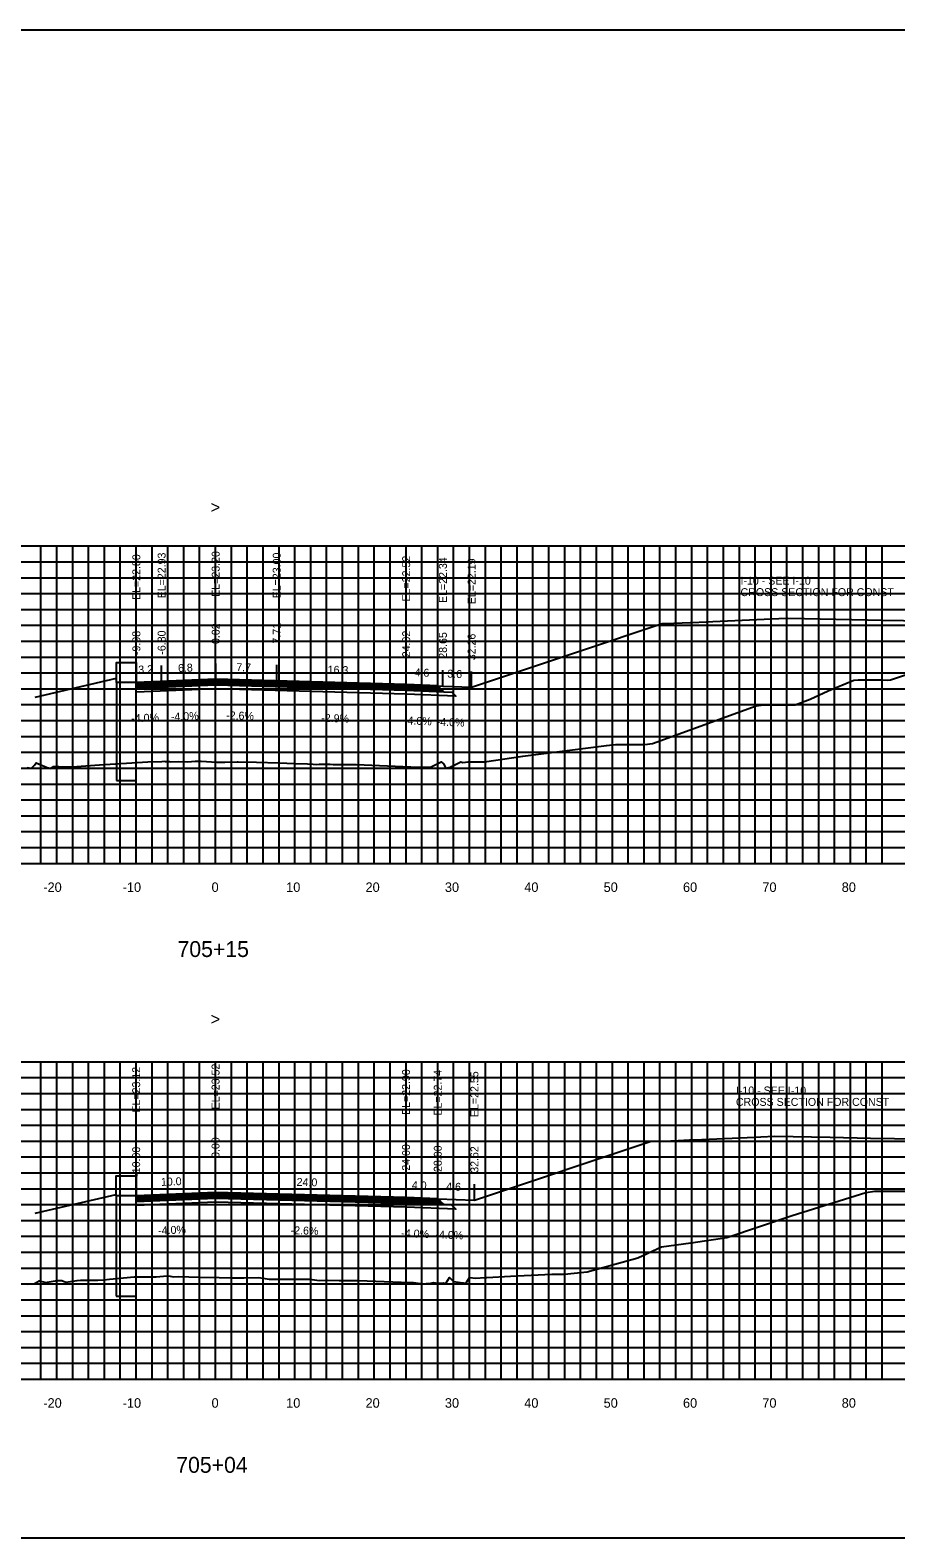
# Model space of a CAD drawing. Extents: x 1797518 to 1804843, y 248068 to 251132.
# Drawn here: x 1803627.6 to 1803736.7, y 250079.4 to 250269.4 of the extents above; entities that cross this region are included whole.
import ezdxf

# ---------------------------------------------------------------- set-up
doc = ezdxf.new("R2010")
doc.units = 0
for name, color, linetype in [('1', 7, 'Continuous'), ('10', 7, 'Continuous'), ('3', 7, 'Continuous'), ('4', 7, 'Continuous'), ('60', 7, 'Continuous'), ('BASE', 7, 'Continuous'), ('CL-CNST', 7, 'Continuous'), ('Level 62', 7, 'Continuous'), ('LOWER BINDER', 7, 'Continuous'), ('M-ROADS', 7, 'Continuous'), ('UPPER BINDER', 7, 'Continuous'), ('WEARING', 7, 'Continuous')]:
    doc.layers.add(name, color=color, linetype=linetype)

msp = doc.modelspace()

# ---------------------------------------------------------------- linework, layer by layer
for p, q in [((1803641.02, 250187.23), (1803641.02, 250189.23)), ((1803644.21, 250187.36), (1803644.21, 250189.36)), ((1803651.02, 250187.63), (1803651.02, 250189.63)), ((1803658.71, 250187.43), (1803658.71, 250189.43)), ((1803675.02, 250186.96), (1803675.02, 250188.96)), ((1803679.65, 250186.77), (1803679.65, 250188.77)), ((1803683.26, 250186.63), (1803683.26, 250188.63)), ((1803641, 250122.55), (1803641, 250124.55)), ((1803651, 250122.95), (1803651, 250124.95)), ((1803675, 250122.33), (1803675, 250124.33)), ((1803679, 250122.17), (1803679, 250124.17)), ((1803683.62, 250121.99), (1803683.62, 250123.99))]:
    msp.add_line(p, q)
msp.add_lwpolyline([(1803501, 250079.43), (1803801, 250079.43), (1803801, 250269.43), (1803501, 250269.43)], close=True)
at = {"layer": '3'}
for p, q in [((1803628.28, 250185.38), (1803638.52, 250187.78)), ((1803628.28, 250120.33), (1803638.5, 250122.72))]:
    msp.add_line(p, q, dxfattribs=at)
at = {"layer": '60'}
for p, q in [((1803501, 250164.43), (1803801, 250164.43)), ((1803631, 250164.37), (1803631, 250164.43)), ((1803641, 250164.37), (1803641, 250164.43)), ((1803651, 250164.37), (1803651, 250164.43)), ((1803661, 250164.37), (1803661, 250164.43)), ((1803671, 250164.37), (1803671, 250164.43)), ((1803681, 250164.37), (1803681, 250164.43)), ((1803691, 250164.37), (1803691, 250164.43)), ((1803701, 250164.37), (1803701, 250164.43)), ((1803711, 250164.37), (1803711, 250164.43)), ((1803721, 250164.37), (1803721, 250164.43)), ((1803731, 250164.37), (1803731, 250164.43)), ((1803501, 250099.43), (1803801, 250099.43)), ((1803631, 250099.37), (1803631, 250099.43)), ((1803641, 250099.37), (1803641, 250099.43)), ((1803651, 250099.37), (1803651, 250099.43)), ((1803661, 250099.37), (1803661, 250099.43)), ((1803671, 250099.37), (1803671, 250099.43)), ((1803681, 250099.37), (1803681, 250099.43)), ((1803691, 250099.37), (1803691, 250099.43)), ((1803701, 250099.37), (1803701, 250099.43)), ((1803711, 250099.37), (1803711, 250099.43)), ((1803721, 250099.37), (1803721, 250099.43)), ((1803731, 250099.37), (1803731, 250099.43))]:
    msp.add_line(p, q, dxfattribs=at)
at = {"layer": 'BASE'}
for points in [[(1803641.02, 250186.51), (1803651.02, 250186.91), (1803675.02, 250186.24), (1803679.77, 250186.05), (1803680.77, 250186.01), (1803681.29, 250185.48), (1803675.02, 250185.74), (1803651.02, 250186.41), (1803641.02, 250186.01)], [(1803641, 250121.83), (1803651, 250122.23), (1803675, 250121.61), (1803679.75, 250121.42), (1803680.75, 250121.38), (1803681.27, 250120.86), (1803675, 250121.11), (1803651, 250121.73), (1803641, 250121.33)]]:
    msp.add_lwpolyline(points, close=True, dxfattribs=at)
at = {"layer": 'CL-CNST'}
for points in [[(1803683.26, 250186.63), (1803696.86, 250191.16), (1803707.29, 250194.64), (1803707.73, 250194.66), (1803710.82, 250194.79), (1803711.03, 250194.8), (1803712.84, 250194.88), (1803713.67, 250194.91), (1803722.92, 250195.31), (1803723.11, 250195.31), (1803725.23, 250195.27), (1803733.17, 250195.12), (1803735.03, 250195.08), (1803742.97, 250194.94)], [(1803641.02, 250187.23), (1803644.21, 250187.36), (1803651.02, 250187.63), (1803658.71, 250187.43), (1803675.02, 250186.96), (1803679.65, 250186.77), (1803683.26, 250186.63)], [(1803683.62, 250121.99), (1803705.77, 250129.37), (1803708.35, 250129.48), (1803709.3, 250129.52), (1803710.74, 250129.59), (1803711.32, 250129.61), (1803717.97, 250129.89), (1803721.42, 250130.04), (1803728.46, 250129.91), (1803733.53, 250129.82), (1803739.57, 250129.71)], [(1803641, 250122.55), (1803651, 250122.95), (1803675, 250122.33), (1803679, 250122.17), (1803683.62, 250121.99)]]:
    msp.add_lwpolyline(points, dxfattribs=at)
for points in [[(1803641.02, 250187.23), (1803638.52, 250187.23), (1803638.52, 250189.73), (1803641.02, 250189.73)], [(1803638.52, 250174.87), (1803641.02, 250174.87), (1803641.02, 250187.23), (1803638.52, 250187.23)], [(1803641, 250122.55), (1803638.5, 250122.55), (1803638.5, 250125.05), (1803641, 250125.05)], [(1803638.5, 250109.87), (1803641, 250109.87), (1803641, 250122.55), (1803638.5, 250122.55)]]:
    msp.add_lwpolyline(points, close=True, dxfattribs=at)
at = {"layer": 'Level 62'}
for p, q in [((1803501, 250204.43), (1803801, 250204.43)), ((1803629, 250164.43), (1803629, 250204.43)), ((1803631, 250164.43), (1803631, 250204.43)), ((1803633, 250164.43), (1803633, 250204.43)), ((1803635, 250164.43), (1803635, 250204.43)), ((1803637, 250164.43), (1803637, 250204.43)), ((1803639, 250164.43), (1803639, 250204.43)), ((1803641, 250164.43), (1803641, 250204.43)), ((1803643, 250164.43), (1803643, 250204.43)), ((1803645, 250164.43), (1803645, 250204.43)), ((1803647, 250164.43), (1803647, 250204.43)), ((1803649, 250164.43), (1803649, 250204.43)), ((1803651, 250164.43), (1803651, 250204.43)), ((1803653, 250164.43), (1803653, 250204.43)), ((1803655, 250164.43), (1803655, 250204.43)), ((1803657, 250164.43), (1803657, 250204.43)), ((1803659, 250164.43), (1803659, 250204.43)), ((1803661, 250164.43), (1803661, 250204.43)), ((1803663, 250164.43), (1803663, 250204.43)), ((1803665, 250164.43), (1803665, 250204.43)), ((1803667, 250164.43), (1803667, 250204.43)), ((1803669, 250164.43), (1803669, 250204.43)), ((1803671, 250164.43), (1803671, 250204.43)), ((1803673, 250164.43), (1803673, 250204.43)), ((1803675, 250164.43), (1803675, 250204.43)), ((1803677, 250164.43), (1803677, 250204.43)), ((1803679, 250164.43), (1803679, 250204.43)), ((1803681, 250164.43), (1803681, 250204.43)), ((1803683, 250164.43), (1803683, 250204.43)), ((1803685, 250164.43), (1803685, 250204.43)), ((1803687, 250164.43), (1803687, 250204.43)), ((1803689, 250164.43), (1803689, 250204.43)), ((1803691, 250164.43), (1803691, 250204.43)), ((1803693, 250164.43), (1803693, 250204.43)), ((1803695, 250164.43), (1803695, 250204.43)), ((1803697, 250164.43), (1803697, 250204.43)), ((1803699, 250164.43), (1803699, 250204.43)), ((1803701, 250164.43), (1803701, 250204.43)), ((1803703, 250164.43), (1803703, 250204.43)), ((1803705, 250164.43), (1803705, 250204.43)), ((1803707, 250164.43), (1803707, 250204.43)), ((1803709, 250164.43), (1803709, 250204.43)), ((1803711, 250164.43), (1803711, 250204.43)), ((1803713, 250164.43), (1803713, 250204.43)), ((1803715, 250164.43), (1803715, 250204.43)), ((1803717, 250164.43), (1803717, 250204.43)), ((1803719, 250164.43), (1803719, 250204.43)), ((1803721, 250164.43), (1803721, 250204.43)), ((1803723, 250164.43), (1803723, 250204.43)), ((1803725, 250164.43), (1803725, 250204.43)), ((1803727, 250164.43), (1803727, 250204.43)), ((1803729, 250164.43), (1803729, 250204.43)), ((1803731, 250164.43), (1803731, 250204.43)), ((1803733, 250164.43), (1803733, 250204.43)), ((1803735, 250164.43), (1803735, 250204.43)), ((1803501, 250202.43), (1803801, 250202.43)), ((1803501, 250200.43), (1803801, 250200.43)), ((1803501, 250198.43), (1803801, 250198.43)), ((1803501, 250196.43), (1803801, 250196.43)), ((1803501, 250194.43), (1803801, 250194.43)), ((1803501, 250192.43), (1803801, 250192.43)), ((1803501, 250190.43), (1803801, 250190.43)), ((1803501, 250188.43), (1803801, 250188.43)), ((1803501, 250186.43), (1803801, 250186.43)), ((1803501, 250184.43), (1803801, 250184.43)), ((1803501, 250182.43), (1803801, 250182.43)), ((1803501, 250180.43), (1803801, 250180.43)), ((1803501, 250178.43), (1803801, 250178.43)), ((1803501, 250176.43), (1803801, 250176.43)), ((1803501, 250174.43), (1803801, 250174.43)), ((1803501, 250172.43), (1803801, 250172.43)), ((1803501, 250170.43), (1803801, 250170.43)), ((1803501, 250168.43), (1803801, 250168.43)), ((1803501, 250166.43), (1803801, 250166.43)), ((1803501, 250164.43), (1803801, 250164.43)), ((1803501, 250139.43), (1803801, 250139.43)), ((1803629, 250099.43), (1803629, 250139.43)), ((1803631, 250099.43), (1803631, 250139.43)), ((1803633, 250099.43), (1803633, 250139.43)), ((1803635, 250099.43), (1803635, 250139.43)), ((1803637, 250099.43), (1803637, 250139.43)), ((1803639, 250099.43), (1803639, 250139.43)), ((1803641, 250099.43), (1803641, 250139.43)), ((1803643, 250099.43), (1803643, 250139.43)), ((1803645, 250099.43), (1803645, 250139.43)), ((1803647, 250099.43), (1803647, 250139.43)), ((1803649, 250099.43), (1803649, 250139.43)), ((1803651, 250099.43), (1803651, 250139.43)), ((1803653, 250099.43), (1803653, 250139.43)), ((1803655, 250099.43), (1803655, 250139.43)), ((1803657, 250099.43), (1803657, 250139.43)), ((1803659, 250099.43), (1803659, 250139.43)), ((1803661, 250099.43), (1803661, 250139.43)), ((1803663, 250099.43), (1803663, 250139.43)), ((1803665, 250099.43), (1803665, 250139.43)), ((1803667, 250099.43), (1803667, 250139.43)), ((1803669, 250099.43), (1803669, 250139.43)), ((1803671, 250099.43), (1803671, 250139.43)), ((1803673, 250099.43), (1803673, 250139.43)), ((1803675, 250099.43), (1803675, 250139.43)), ((1803677, 250099.43), (1803677, 250139.43)), ((1803679, 250099.43), (1803679, 250139.43)), ((1803681, 250099.43), (1803681, 250139.43)), ((1803683, 250099.43), (1803683, 250139.43)), ((1803685, 250099.43), (1803685, 250139.43)), ((1803687, 250099.43), (1803687, 250139.43)), ((1803689, 250099.43), (1803689, 250139.43)), ((1803691, 250099.43), (1803691, 250139.43)), ((1803693, 250099.43), (1803693, 250139.43)), ((1803695, 250099.43), (1803695, 250139.43)), ((1803697, 250099.43), (1803697, 250139.43)), ((1803699, 250099.43), (1803699, 250139.43)), ((1803701, 250099.43), (1803701, 250139.43)), ((1803703, 250099.43), (1803703, 250139.43)), ((1803705, 250099.43), (1803705, 250139.43)), ((1803707, 250099.43), (1803707, 250139.43)), ((1803709, 250099.43), (1803709, 250139.43)), ((1803711, 250099.43), (1803711, 250139.43)), ((1803713, 250099.43), (1803713, 250139.43)), ((1803715, 250099.43), (1803715, 250139.43)), ((1803717, 250099.43), (1803717, 250139.43)), ((1803719, 250099.43), (1803719, 250139.43)), ((1803721, 250099.43), (1803721, 250139.43)), ((1803723, 250099.43), (1803723, 250139.43)), ((1803725, 250099.43), (1803725, 250139.43)), ((1803727, 250099.43), (1803727, 250139.43)), ((1803729, 250099.43), (1803729, 250139.43)), ((1803731, 250099.43), (1803731, 250139.43)), ((1803733, 250099.43), (1803733, 250139.43)), ((1803735, 250099.43), (1803735, 250139.43)), ((1803501, 250137.43), (1803801, 250137.43)), ((1803501, 250135.43), (1803801, 250135.43)), ((1803501, 250133.43), (1803801, 250133.43)), ((1803501, 250131.43), (1803801, 250131.43)), ((1803501, 250129.43), (1803801, 250129.43)), ((1803501, 250127.43), (1803801, 250127.43)), ((1803501, 250125.43), (1803801, 250125.43)), ((1803501, 250123.43), (1803801, 250123.43)), ((1803501, 250121.43), (1803801, 250121.43)), ((1803501, 250119.43), (1803801, 250119.43)), ((1803501, 250117.43), (1803801, 250117.43)), ((1803501, 250115.43), (1803801, 250115.43)), ((1803501, 250113.43), (1803801, 250113.43)), ((1803501, 250111.43), (1803801, 250111.43)), ((1803501, 250109.43), (1803801, 250109.43)), ((1803501, 250107.43), (1803801, 250107.43)), ((1803501, 250105.43), (1803801, 250105.43)), ((1803501, 250103.43), (1803801, 250103.43)), ((1803501, 250101.43), (1803801, 250101.43)), ((1803501, 250099.43), (1803801, 250099.43))]:
    msp.add_line(p, q, dxfattribs=at)
at = {"layer": 'LOWER BINDER'}
for points in [[(1803651.02, 250187.29), (1803675.02, 250186.62), (1803679.37, 250186.44), (1803679.57, 250186.24), (1803675.02, 250186.43), (1803651.02, 250187.1), (1803641.02, 250186.7), (1803641.02, 250186.89)], [(1803651.02, 250187.1), (1803675.02, 250186.43), (1803679.57, 250186.24), (1803679.77, 250186.05), (1803675.02, 250186.24), (1803651.02, 250186.91), (1803641.02, 250186.51), (1803641.02, 250186.7)], [(1803651, 250122.61), (1803675, 250121.99), (1803679.36, 250121.82), (1803679.55, 250121.62), (1803675, 250121.8), (1803651, 250122.42), (1803641, 250122.02), (1803641, 250122.21)], [(1803651, 250122.42), (1803675, 250121.8), (1803679.55, 250121.62), (1803679.75, 250121.42), (1803675, 250121.61), (1803651, 250122.23), (1803641, 250121.83), (1803641, 250122.02)]]:
    msp.add_lwpolyline(points, close=True, dxfattribs=at)
at = {"layer": 'M-ROADS'}
for points in [[(1803627.25, 250176.53), (1803627.8, 250176.44), (1803628.2, 250176.8), (1803628.4, 250177.12), (1803629.79, 250176.51), (1803630.23, 250176.39), (1803630.29, 250176.43), (1803630.58, 250176.62), (1803631.24, 250176.62), (1803632.94, 250176.61), (1803636.36, 250176.84), (1803642.49, 250177.24), (1803644.23, 250177.28), (1803644.6, 250177.29), (1803644.67, 250177.28), (1803644.82, 250177.28), (1803645.2, 250177.25), (1803645.38, 250177.24), (1803646.34, 250177.25), (1803647.49, 250177.24), (1803648.42, 250177.31), (1803648.65, 250177.33), (1803649.17, 250177.3), (1803651.18, 250177.2), (1803652.19, 250177.2), (1803653.73, 250177.21), (1803653.84, 250177.21), (1803656.18, 250177.2), (1803658.97, 250177.1), (1803660.99, 250177.02), (1803662.6, 250176.96), (1803663.31, 250176.92), (1803663.76, 250176.89), (1803664.06, 250176.92), (1803665.43, 250176.94), (1803665.84, 250176.91), (1803666.29, 250176.9), (1803666.54, 250176.91), (1803668.37, 250176.91), (1803668.76, 250176.89), (1803675.56, 250176.58), (1803675.66, 250176.57), (1803675.66, 250176.57), (1803675.67, 250176.57), (1803678.16, 250176.57), (1803678.19, 250176.6), (1803679.41, 250177.22), (1803679.71, 250176.96), (1803680.01, 250176.43), (1803680.61, 250176.56), (1803680.73, 250176.62), (1803681.9, 250177.22), (1803682.17, 250177.13), (1803682.85, 250177.22), (1803684.38, 250177.22), (1803684.56, 250177.23), (1803684.88, 250177.24), (1803689.72, 250177.93), (1803700.27, 250179.29), (1803701.41, 250179.43), (1803703.24, 250179.43), (1803705.1, 250179.43), (1803706.05, 250179.55), (1803719.11, 250184.27), (1803720.06, 250184.42), (1803722.04, 250184.42), (1803724.05, 250184.42), (1803725.93, 250185.11), (1803728.2, 250186.17), (1803731.43, 250187.53), (1803731.99, 250187.58), (1803733.57, 250187.58), (1803735.1, 250187.58), (1803735.63, 250187.53), (1803736.04, 250187.56), (1803744.32, 250190.34)], [(1803627.36, 250111.41), (1803628.2, 250111.5), (1803628.76, 250111.84), (1803629.5, 250111.64), (1803629.73, 250111.63), (1803629.8, 250111.64), (1803631.06, 250111.85), (1803631.62, 250111.85), (1803632.12, 250111.65), (1803633.55, 250111.85), (1803634, 250111.9), (1803636.16, 250111.9), (1803636.91, 250111.95), (1803637.63, 250112.02), (1803640.76, 250112.33), (1803642.32, 250112.32), (1803642.88, 250112.32), (1803642.98, 250112.32), (1803643.2, 250112.32), (1803643.51, 250112.33), (1803644.43, 250112.41), (1803645.02, 250112.44), (1803645.76, 250112.33), (1803646.3, 250112.37), (1803648.96, 250112.27), (1803651.46, 250112.22), (1803652.93, 250112.21), (1803653.98, 250112.21), (1803654.6, 250112.21), (1803656.46, 250112.22), (1803657.77, 250112.04), (1803657.8, 250112.03), (1803657.84, 250112.03), (1803660.31, 250112.03), (1803662.78, 250112.03), (1803662.83, 250112.03), (1803662.88, 250112.02), (1803664.05, 250111.88), (1803665.11, 250111.89), (1803666.58, 250111.87), (1803666.77, 250111.86), (1803669.05, 250111.88), (1803674.38, 250111.66), (1803675.94, 250111.6), (1803677.15, 250111.46), (1803677.56, 250111.48), (1803678.11, 250111.54), (1803678.48, 250111.59), (1803678.96, 250111.54), (1803679.67, 250111.56), (1803680.01, 250111.46), (1803680.08, 250111.56), (1803680.49, 250112.24), (1803681, 250111.73), (1803682.17, 250111.56), (1803682.22, 250111.55), (1803682.41, 250111.53), (1803682.58, 250111.56), (1803682.99, 250112.24), (1803683.79, 250112.17), (1803684.92, 250112.24), (1803685.2, 250112.26), (1803688.18, 250112.39), (1803693.39, 250112.66), (1803694.17, 250112.66), (1803694.96, 250112.66), (1803697.82, 250112.97), (1803704.2, 250114.7), (1803707.21, 250116.12), (1803710.87, 250116.63), (1803710.9, 250116.63), (1803710.93, 250116.63), (1803715.41, 250117.28), (1803723.66, 250120.07), (1803732.92, 250122.96), (1803734.07, 250123.12), (1803735.97, 250123.12), (1803737.87, 250123.12)]]:
    msp.add_lwpolyline(points, dxfattribs=at)
at = {"layer": 'UPPER BINDER'}
for points in [[(1803679.37, 250186.44), (1803679.17, 250186.64), (1803675.02, 250186.81), (1803651.02, 250187.48), (1803641.02, 250187.08), (1803641.02, 250186.89), (1803651.02, 250187.29), (1803675.02, 250186.62)], [(1803679.36, 250121.82), (1803679.16, 250122.01), (1803675, 250122.18), (1803651, 250122.8), (1803641, 250122.4), (1803641, 250122.21), (1803651, 250122.61), (1803675, 250121.99)]]:
    msp.add_lwpolyline(points, close=True, dxfattribs=at)
at = {"layer": 'WEARING'}
for points in [[(1803679.17, 250186.64), (1803679.02, 250186.8), (1803675.02, 250186.96), (1803651.02, 250187.63), (1803651.02, 250187.63), (1803641.02, 250187.23), (1803641.02, 250187.08), (1803651.02, 250187.48), (1803675.02, 250186.81)], [(1803679.16, 250122.01), (1803679, 250122.17), (1803675, 250122.33), (1803651, 250122.95), (1803651, 250122.95), (1803641, 250122.55), (1803641, 250122.4), (1803651, 250122.8), (1803675, 250122.18)]]:
    msp.add_lwpolyline(points, close=True, dxfattribs=at)

# ---------------------------------------------------------------- texts
at = {"layer": '1'}
for s, p in [('705+15', (1803646.21, 250152.63)), ('705+04', (1803646.05, 250087.63))]:
    msp.add_text(s, height=2, dxfattribs=at).set_placement(p)
at = {"layer": '10'}
for s, p in [('-20', (1803629.3, 250160.83)), ('-10', (1803639.3, 250160.83)), ('0', (1803650.5, 250160.83)), ('10', (1803659.9, 250160.83)), ('20', (1803669.9, 250160.83)), ('30', (1803679.9, 250160.83)), ('40', (1803689.9, 250160.83)), ('50', (1803699.9, 250160.83)), ('60', (1803709.9, 250160.83)), ('70', (1803719.9, 250160.83)), ('80', (1803729.9, 250160.83)), ('-20', (1803629.3, 250095.83)), ('-10', (1803639.3, 250095.83)), ('0', (1803650.5, 250095.83)), ('10', (1803659.9, 250095.83)), ('20', (1803669.9, 250095.83)), ('30', (1803679.9, 250095.83)), ('40', (1803689.9, 250095.83)), ('50', (1803699.9, 250095.83)), ('60', (1803709.9, 250095.83)), ('70', (1803719.9, 250095.83)), ('80', (1803729.9, 250095.83))]:
    msp.add_text(s, height=1.2, dxfattribs=at).set_placement(p)
at = {"layer": '3'}
for s, p in [('EL=22.93', (1803644.71, 250197.83)), ('EL=23.20', (1803651.52, 250198.02)), ('EL=23.00', (1803659.21, 250197.83)), ('EL=22.80', (1803641.52, 250197.62)), ('EL=22.52', (1803675.52, 250197.43)), ('EL=22.34', (1803680.15, 250197.24)), ('EL=22.19', (1803683.76, 250197.1)), ('0.02', (1803651.52, 250192.07)), ('7.71', (1803659.21, 250192.13)), ('-9.98', (1803641.52, 250190.68)), ('-6.80', (1803644.71, 250190.73)), ('24.02', (1803675.52, 250190.4)), ('28.65', (1803680.15, 250190.22)), ('32.26', (1803683.76, 250190.03)), ('EL=23.52', (1803651.5, 250133.42)), ('EL=23.12', (1803641.5, 250133.02)), ('EL=22.90', (1803675.5, 250132.72)), ('EL=22.74', (1803679.5, 250132.64)), ('EL=22.55', (1803684.12, 250132.46)), ('0.00', (1803651.5, 250127.31)), ('-10.00', (1803641.5, 250124.93)), ('24.00', (1803675.5, 250125.7)), ('28.00', (1803679.5, 250125.54)), ('32.62', (1803684.12, 250125.44))]:
    msp.add_text(s, height=1, rotation=90, dxfattribs=at).set_placement(p)
for s, p in [('I-10 - SEE I-10', (1803717.15, 250199.55)), ('CROSS SECTION FOR CONST ', (1803717.15, 250198.11)), ('I-10 - SEE I-10', (1803716.57, 250135.31)), ('CROSS SECTION FOR CONST ', (1803716.57, 250133.87))]:
    msp.add_text(s, height=1, dxfattribs=at).set_placement(p)
at = {"layer": '4'}
for s, rotation, p in [('3.2', 2.2997, (1803641.29, 250188.34)), ('6.8', 2.2864, (1803646.29, 250188.54)), ('7.7', 358.535, (1803653.61, 250188.66)), ('16.3', 358.3224, (1803665.12, 250188.35)), ('4.6', 357.7109, (1803676.07, 250188.01)), ('3.6', 357.7043, (1803680.19, 250187.85)), ('-4.0%', 2.2997, (1803640.4, 250182.2)), ('-4.0%', 2.2864, (1803645.4, 250182.4)), ('-2.6%', 358.535, (1803652.33, 250182.59)), ('-2.9%', 358.3224, (1803664.31, 250182.27)), ('-4.0%', 357.7109, (1803674.73, 250181.96)), ('-4.0%', 357.7043, (1803678.85, 250181.8)), ('10.0', 2.2906, (1803644.14, 250123.78)), ('24.0', 358.5259, (1803661.21, 250123.79)), ('4.0', 357.7094, (1803675.72, 250123.4)), ('4.6', 357.7094, (1803680.05, 250123.23)), ('-4.0%', 2.2906, (1803643.79, 250117.66)), ('-2.6%', 358.5259, (1803660.46, 250117.7)), ('-4.0%', 357.7094, (1803674.39, 250117.35)), ('-4.0%', 357.7094, (1803678.7, 250117.18))]:
    msp.add_text(s, height=1, rotation=rotation, dxfattribs=at).set_placement(p)
at = {"layer": '60'}
for p in [(1803650.39, 250208.57), (1803650.39, 250144.07)]:
    msp.add_text('>', height=1.5, dxfattribs=at).set_placement(p)

doc.saveas('drawing.dxf')
